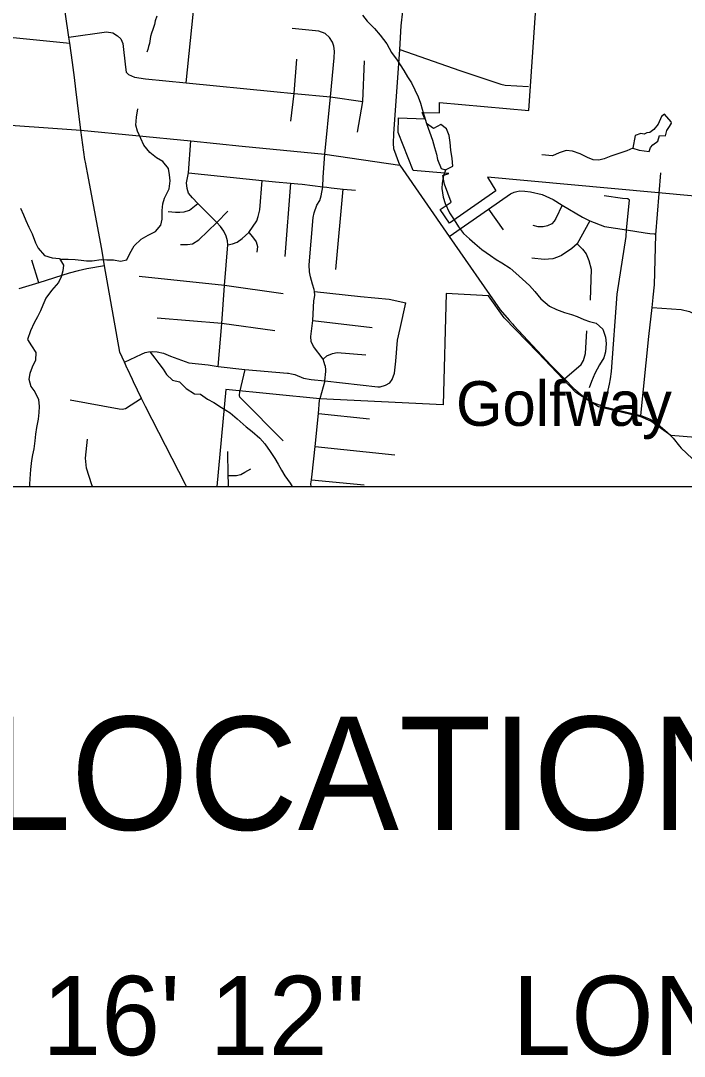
# Model space of a CAD drawing. Extents: x 0 to 34, y 0 to 22.
# Drawn here: x 4.429 to 5.602, y 13.194 to 15.023 of the extents above; entities that cross this region are included whole.
import ezdxf

# ---------------------------------------------------------------- set-up
doc = ezdxf.new("R2010")
doc.units = 0
for name, color, linetype in [('GM_X_City_Street', 7, 'Continuous'), ('GM_X_Corporation', 7, 'Continuous'), ('GM_X_County_Road', 7, 'Continuous'), ('GM_X_Minor_Lake', 7, 'Continuous'), ('GM_X_Minor_River', 7, 'Continuous'), ('GM_X_Township_ROW', 7, 'Continuous'), ('GM_X_Township_Subdivision', 7, 'Continuous'), ('GM_X_Unincorporated_Text', 7, 'Continuous'), ('GM_X_US_Route', 7, 'Continuous'), ('SH_Data', 7, 'Continuous')]:
    doc.layers.add(name, color=color, linetype=linetype)

msp = doc.modelspace()

# ---------------------------------------------------------------- linework, layer by layer
at = {"layer": 'GM_X_City_Street'}
for points in [[(4.8158, 14.3669), (4.8153, 14.3623), (4.8153, 14.3613), (4.8154, 14.3604), (4.8157, 14.3594), (4.816, 14.3588), (4.8185, 14.356), (4.8927, 14.2811)], [(4.9426, 14.2), (4.9417, 14.2051), (4.9428, 14.212), (4.9443, 14.222), (4.9492, 14.2708), (4.9551, 14.3294), (4.9574, 14.353), (4.9577, 14.3554)], [(4.9551, 14.3294), (5.0453, 14.3199)], [(4.9492, 14.2708), (5.0904, 14.2564)], [(5.5934, 14.2713), (5.5961, 14.2678), (5.6155, 14.2498), (5.6358, 14.2115), (5.6405, 14.2)], [(4.7969, 14.2), (4.7964, 14.2007), (4.7962, 14.2064), (4.7959, 14.2197), (4.7949, 14.2619)], [(4.7959, 14.2197), (4.8102, 14.2197), (4.8151, 14.2207), (4.8182, 14.2214), (4.825, 14.2254), (4.8359, 14.2316)], [(4.9428, 14.212), (5.0363, 14.2035)]]:
    msp.add_lwpolyline(points, dxfattribs=at)
at = {"layer": 'GM_X_Corporation'}
msp.add_line((4.7755, 14.2), (7.1307, 14.2), dxfattribs=at)
for points in [[(6.9956, 14.8531), (6.7125, 14.887), (6.701, 14.6468), (6.473, 14.6817), (6.4728, 14.6434), (5.9933, 14.679), (5.254, 14.7467), (5.2688, 14.7224), (5.187, 14.6653), (5.1701, 14.6893), (5.1899, 14.7022), (5.1782, 14.7342), (5.1751, 14.7498), (5.1856, 14.7529), (5.1229, 14.7587), (5.0962, 14.8253), (5.0967, 14.8513), (5.1434, 14.8494), (5.1387, 14.8608), (5.1692, 14.8604), (5.1692, 14.8783), (5.3269, 14.8644), (5.36, 15.3466)], [(6.9956, 14.8531), (6.7125, 14.887), (6.701, 14.6468), (6.473, 14.6817), (6.4728, 14.6434), (5.9933, 14.679), (5.9556, 14.2595), (5.5778, 14.2901), (5.5429, 14.3154), (5.5247, 14.3232), (5.4502, 14.341), (5.4099, 14.3661), (5.3427, 14.4372), (5.2834, 14.4983), (5.256, 14.5372), (5.1809, 14.5414), (5.1758, 14.3448), (4.9577, 14.3554), (4.7915, 14.3718), (4.7755, 14.2)]]:
    msp.add_lwpolyline(points, dxfattribs=at)
at = {"layer": 'GM_X_County_Road'}
for points in [[(5.0993, 14.7678), (5.0886, 14.7969), (5.0877, 14.8064), (5.0885, 14.8231), (5.0988, 14.9724), (5.1017, 15.0142), (5.1101, 15.0924)], [(4.0583, 14.9068), (4.0642, 14.9062), (4.1976, 14.8897), (4.2818, 14.8811), (4.2881, 14.8783), (4.2964, 14.8747), (4.3359, 14.8464), (4.3446, 14.8435), (4.3609, 14.8419), (4.5356, 14.8298)], [(4.5356, 14.8298), (4.7297, 14.8106), (4.8202, 14.8014), (4.9663, 14.7871), (5.0993, 14.7678)], [(5.0993, 14.7678), (5.1865, 14.6418), (5.2762, 14.5124), (5.2922, 14.4942), (5.2988, 14.4868)], [(5.2988, 14.4868), (5.3005, 14.4848), (5.3666, 14.4142), (5.39, 14.3902), (5.4068, 14.3731), (5.4213, 14.3611), (5.4388, 14.3493), (5.4588, 14.3415), (5.4609, 14.341), (5.525, 14.3259), (5.5412, 14.3193), (5.5527, 14.3119), (5.56, 14.306), (5.5714, 14.2962), (5.5823, 14.2858), (5.5934, 14.2713)]]:
    msp.add_lwpolyline(points, dxfattribs=at)
at = {"layer": 'GM_X_Minor_Lake'}
for points in [[(5.5107, 14.7981), (5.5218, 14.7946), (5.5395, 14.7919), (5.542, 14.7991), (5.5463, 14.8035), (5.5551, 14.8102), (5.558, 14.82), (5.5687, 14.8198), (5.5708, 14.8288), (5.5759, 14.8363), (5.579, 14.8419), (5.5783, 14.8442), (5.5668, 14.8581), (5.5614, 14.8537), (5.5554, 14.8402), (5.548, 14.8308), (5.5407, 14.8257), (5.5357, 14.825), (5.5311, 14.8225), (5.5247, 14.8238), (5.5151, 14.8202)], [(5.1462, 14.8416), (5.1569, 14.812), (5.1604, 14.799), (5.1639, 14.7875), (5.1659, 14.778), (5.172, 14.7618), (5.1796, 14.7594)], [(5.1796, 14.7594), (5.1926, 14.7659), (5.1914, 14.7796), (5.1895, 14.7945), (5.1883, 14.8078), (5.1864, 14.8201), (5.1817, 14.832), (5.1716, 14.8394), (5.1585, 14.8325), (5.1462, 14.8416)], [(5.5151, 14.8202), (5.5107, 14.7981)]]:
    msp.add_lwpolyline(points, dxfattribs=at)
at = {"layer": 'GM_X_Minor_River'}
for points in [[(4.6696, 15.0309), (4.6667, 15.0226), (4.6654, 15.0162), (4.6628, 15.0075), (4.6604, 15.0011), (4.6583, 14.995), (4.657, 14.9871), (4.6565, 14.9825), (4.6552, 14.9772), (4.6539, 14.9723), (4.6519, 14.9674)], [(5.0331, 15.0326), (5.0415, 15.0221), (5.0541, 15.0092), (5.0641, 14.9976), (5.0759, 14.9821), (5.0843, 14.967), (5.0946, 14.9535), (5.1063, 14.935), (5.1129, 14.9238), (5.1198, 14.9133), (5.1314, 14.8887), (5.1357, 14.8776), (5.1388, 14.8665), (5.142, 14.855), (5.1462, 14.8416)], [(4.4991, 14.6003), (4.502, 14.6021), (4.513, 14.6018), (4.5255, 14.6011), (4.5358, 14.6001), (4.5456, 14.5991), (4.5551, 14.5989), (4.5715, 14.6015), (4.581, 14.6009), (4.5931, 14.6006), (4.6056, 14.598), (4.6167, 14.6008), (4.6219, 14.6117), (4.6295, 14.6256), (4.6419, 14.6374), (4.6542, 14.644), (4.6673, 14.6505), (4.6767, 14.6617), (4.6789, 14.6723), (4.6792, 14.6879), (4.6803, 14.6993), (4.6832, 14.7098), (4.6916, 14.726), (4.6931, 14.74), (4.6922, 14.7507), (4.6902, 14.7618), (4.6802, 14.7742), (4.6693, 14.7809), (4.657, 14.7903), (4.6467, 14.8031), (4.6413, 14.815), (4.6355, 14.8281), (4.6327, 14.8385), (4.6338, 14.8525), (4.6361, 14.8673)], [(5.5107, 14.7981), (5.5003, 14.793), (5.4846, 14.7881), (5.472, 14.7838), (5.4601, 14.7792), (5.4505, 14.7767), (5.441, 14.777), (5.4305, 14.7814), (5.4178, 14.7878), (5.4042, 14.7927), (5.3928, 14.7937), (5.3806, 14.7895), (5.3687, 14.7844), (5.3501, 14.786)], [(5.1805, 14.7599), (5.1763, 14.7496), (5.1737, 14.7359), (5.1731, 14.7265), (5.1757, 14.7112), (5.1793, 14.7001), (5.1868, 14.6839), (5.1949, 14.6712), (5.2026, 14.6588), (5.2118, 14.6472), (5.2222, 14.6378), (5.2319, 14.6292), (5.2442, 14.6186), (5.2595, 14.608), (5.2696, 14.6013), (5.2793, 14.5953), (5.2939, 14.5859), (5.3043, 14.5772), (5.3159, 14.5663), (5.3285, 14.5554), (5.3377, 14.5445), (5.3485, 14.532), (5.3637, 14.5187), (5.3757, 14.5128), (5.39, 14.5075), (5.4025, 14.5041), (5.4123, 14.5005), (5.4243, 14.4952), (5.4341, 14.4919), (5.4462, 14.4886), (5.4581, 14.478), (5.4623, 14.4639), (5.4636, 14.4528), (5.4625, 14.4384), (5.4595, 14.4274), (5.452, 14.4154), (5.4437, 14.3997), (5.438, 14.3858), (5.4339, 14.3744)], [(4.4285, 14.6917), (4.4343, 14.6801), (4.4383, 14.6702), (4.4437, 14.6582), (4.4495, 14.6463), (4.4555, 14.6306), (4.4599, 14.621), (4.4713, 14.6081), (4.4845, 14.604), (4.4974, 14.6029), (4.5047, 14.591), (4.5034, 14.5811), (4.5008, 14.5705), (4.496, 14.5607), (4.4835, 14.5462), (4.4733, 14.5328), (4.4681, 14.5207), (4.464, 14.5106), (4.4585, 14.5001), (4.4529, 14.4892), (4.4461, 14.4753), (4.4412, 14.4602), (4.4481, 14.4486), (4.4558, 14.437), (4.4551, 14.4237), (4.4495, 14.4113), (4.4454, 14.4), (4.4436, 14.3901), (4.4471, 14.3771), (4.4541, 14.3675), (4.4606, 14.354), (4.4618, 14.3414), (4.4612, 14.3308), (4.4598, 14.3194), (4.4571, 14.3046), (4.4553, 14.2929), (4.4543, 14.2811), (4.452, 14.2667), (4.4499, 14.2561), (4.4481, 14.2463), (4.4462, 14.2304), (4.4451, 14.2137), (4.4448, 14.2042), (4.4449, 14.2)], [(4.658, 14.4378), (4.6661, 14.4269), (4.6731, 14.4173), (4.6808, 14.4076), (4.6867, 14.3979), (4.6974, 14.3878), (4.7095, 14.3852), (4.7214, 14.3731), (4.736, 14.364), (4.7466, 14.3634), (4.7593, 14.3543), (4.7706, 14.3484), (4.784, 14.3397), (4.799, 14.3302), (4.8117, 14.32), (4.8277, 14.3059), (4.8381, 14.2973), (4.8519, 14.2855), (4.8604, 14.2758), (4.8699, 14.2619), (4.878, 14.2499), (4.8838, 14.2395), (4.89, 14.2291), (4.8959, 14.2191), (4.9051, 14.2059), (4.9086, 14.2)]]:
    msp.add_lwpolyline(points, dxfattribs=at)
at = {"layer": 'GM_X_Township_ROW'}
msp.add_lwpolyline([(5.5514, 14.6447), (5.5601, 14.7544)], dxfattribs=at)
at = {"layer": 'GM_X_Township_Subdivision'}
for points in [[(4.7213, 14.9134), (4.7368, 15.0634)], [(4.5144, 14.9937), (4.5806, 15.0034), (4.5916, 15.0014), (4.6001, 14.9964), (4.6058, 14.9909), (4.6098, 14.9829), (4.6143, 14.9412), (4.6153, 14.9319), (4.6193, 14.9277), (4.6303, 14.9232), (4.6496, 14.9204), (4.7213, 14.9134), (4.8763, 14.8977), (4.9125, 14.8942), (4.9763, 14.8887), (5.0335, 14.8802)], [(4.948, 14.5339), (4.9486, 14.5383), (4.948, 14.5448), (4.9477, 14.5482), (4.9445, 14.5578), (4.9411, 14.5708), (4.9394, 14.5792), (4.9386, 14.5918), (4.946, 14.6755), (4.9477, 14.6834), (4.9522, 14.697), (4.9577, 14.7057), (4.9601, 14.7136), (4.9629, 14.7298), (4.9636, 14.7466), (4.9663, 14.7871), (4.9763, 14.8887), (4.9828, 14.9574), (4.9835, 14.9691), (4.9823, 14.9779), (4.9798, 14.9851), (4.9748, 14.9936), (4.9673, 15.0001), (4.9558, 15.0046), (4.909, 15.0094)], [(4.4039, 14.9946), (4.5159, 14.9833)], [(5.0988, 14.9724), (5.2052, 14.9349), (5.2778, 14.9111), (5.285, 14.9094), (5.3266, 14.9065)], [(4.9062, 14.8455), (4.9125, 14.8942), (4.9168, 14.9549)], [(5.0241, 14.8259), (5.0335, 14.8802), (5.0364, 14.952)], [(4.778, 14.4122), (4.7846, 14.4883), (4.7893, 14.5551), (4.7949, 14.6269), (4.7948, 14.6341), (4.792, 14.6426), (4.7882, 14.6512), (4.7823, 14.6597), (4.7757, 14.6663), (4.7423, 14.7), (4.7327, 14.71), (4.7259, 14.7182), (4.7235, 14.7265), (4.722, 14.7368), (4.7257, 14.7543), (4.7297, 14.8106)], [(4.7257, 14.7543), (4.8558, 14.741), (4.8793, 14.7383), (4.9056, 14.7358), (4.919, 14.7346)], [(4.7949, 14.6269), (4.8031, 14.6288), (4.8116, 14.6317), (4.8207, 14.6384), (4.832, 14.649), (4.8462, 14.6696), (4.8487, 14.6772), (4.8517, 14.6892), (4.8558, 14.741)], [(4.9056, 14.7358), (4.8956, 14.6064)], [(4.919, 14.7346), (4.9262, 14.734), (4.9629, 14.7298), (4.9698, 14.729)], [(4.9698, 14.729), (4.978, 14.728), (4.999, 14.7254), (5.0206, 14.7234)], [(4.9862, 14.5837), (4.999, 14.7254)], [(5.1865, 14.6418), (5.2558, 14.6899), (5.2945, 14.7171), (5.3011, 14.7201), (5.3058, 14.7213), (5.3112, 14.7226)], [(5.3112, 14.7226), (5.32, 14.7219), (5.3302, 14.721), (5.3507, 14.7158), (5.37, 14.7072), (5.3858, 14.6971), (5.4218, 14.676), (5.4348, 14.6698), (5.4605, 14.6593), (5.4997, 14.6534), (5.5325, 14.6485), (5.5411, 14.6473), (5.5489, 14.6463), (5.5505, 14.6455), (5.5512, 14.6449), (5.5514, 14.6447)], [(5.4609, 14.341), (5.4694, 14.3808), (5.4714, 14.3907), (5.4731, 14.4032), (5.4832, 14.5398), (5.499, 14.6416), (5.4997, 14.6534), (5.5052, 14.706), (5.5018, 14.7085), (5.4927, 14.7092), (5.4604, 14.7136)], [(4.6894, 14.686), (4.7028, 14.6851), (4.7103, 14.6848), (4.7182, 14.6854), (4.7272, 14.6882), (4.7423, 14.7)], [(5.2558, 14.6899), (5.2816, 14.6534)], [(5.3858, 14.6971), (5.3746, 14.6735), (5.3718, 14.669), (5.3676, 14.6645), (5.36, 14.6608), (5.3524, 14.6588), (5.3434, 14.6592), (5.3348, 14.661)], [(4.7116, 14.6275), (4.7239, 14.628), (4.7326, 14.6291), (4.744, 14.6361), (4.7757, 14.6663), (4.7952, 14.6868)], [(5.4348, 14.6698), (5.4127, 14.6288), (5.4032, 14.6206), (5.3849, 14.6082), (5.378, 14.6052), (5.3697, 14.6025), (5.3541, 14.6013), (5.3326, 14.6035)], [(4.832, 14.649), (4.8388, 14.6411), (4.8454, 14.6326), (4.8478, 14.6244), (4.8465, 14.6139)], [(5.547, 14.5345), (5.5494, 14.5562), (5.5514, 14.6447)], [(5.4127, 14.6288), (5.4218, 14.6196), (5.4282, 14.6111), (5.4331, 14.5995), (5.4372, 14.5843), (5.4352, 14.5291)], [(4.4611, 14.5601), (4.4485, 14.6001)], [(4.5769, 14.5898), (4.5457, 14.5846), (4.5306, 14.5813), (4.5149, 14.5768), (4.4611, 14.5601), (4.426, 14.5494)], [(4.8929, 14.5405), (4.7893, 14.5551), (4.6387, 14.5711)], [(4.948, 14.5448), (5.0294, 14.5356), (5.0801, 14.5313), (5.1095, 14.5245)], [(4.9024, 14.4004), (4.9077, 14.3994), (4.9135, 14.3983), (4.9291, 14.3918), (4.9422, 14.389), (4.9668, 14.3867), (5.0602, 14.3763), (5.0644, 14.3764), (5.074, 14.3794), (5.0815, 14.3832), (5.0858, 14.3891), (5.0899, 14.4005), (5.0923, 14.4215), (5.095, 14.4587), (5.0997, 14.4795), (5.1095, 14.5245)], [(4.9668, 14.3867), (4.9683, 14.4033), (4.9682, 14.4071), (4.9675, 14.4123), (4.9666, 14.4154), (4.9653, 14.4194), (4.9635, 14.4249), (4.9468, 14.4478), (4.9425, 14.4564), (4.9418, 14.4653), (4.9455, 14.4933), (4.9471, 14.5281), (4.948, 14.5339)], [(5.525, 14.3259), (5.5393, 14.4652), (5.545, 14.5162), (5.547, 14.5343), (5.547, 14.5345)], [(5.545, 14.5162), (5.5961, 14.5129), (5.6111, 14.5096), (5.6215, 14.5038), (5.6286, 14.494), (5.6354, 14.4771), (5.6429, 14.4654), (5.6507, 14.4615), (5.6608, 14.4589), (5.6803, 14.4563), (5.7698, 14.4494)], [(4.878, 14.4751), (4.7846, 14.4883), (4.6702, 14.4974)], [(4.9455, 14.4933), (5.05, 14.4811)], [(5.39, 14.3902), (5.4197, 14.416), (5.4234, 14.4231), (5.4269, 14.435), (5.4294, 14.4752)], [(4.6123, 14.4199), (4.6428, 14.4339), (4.6493, 14.4367), (4.6552, 14.4383), (4.6622, 14.4387), (4.6703, 14.4383), (4.6813, 14.4359), (4.6938, 14.4304), (4.7264, 14.4188), (4.7606, 14.4149), (4.778, 14.4122), (4.8252, 14.4072), (4.9008, 14.4007), (4.9024, 14.4004)], [(4.9635, 14.4249), (4.9701, 14.4308), (4.98, 14.4353), (4.9884, 14.437), (5.0392, 14.4331)], [(4.8252, 14.4072), (4.8158, 14.3669)], [(4.9668, 14.3867), (4.9577, 14.3554)], [(4.6428, 14.3557), (4.614, 14.3373), (4.6082, 14.336), (4.603, 14.3367), (4.5162, 14.3529)], [(4.5558, 14.2), (4.5545, 14.2035), (4.5454, 14.2324), (4.5434, 14.2501), (4.5471, 14.2836)]]:
    msp.add_lwpolyline(points, dxfattribs=at)
at = {"layer": 'GM_X_US_Route'}
for points in [[(4.5242, 14.9225), (4.5208, 14.9494), (4.5159, 14.9833), (4.5144, 14.9937), (4.4954, 15.1244), (4.4862, 15.1877), (4.4752, 15.2718), (4.4644, 15.355), (4.4625, 15.3694), (4.4601, 15.3824), (4.4536, 15.436), (4.4509, 15.4477), (4.4494, 15.4539)], [(4.5267, 14.9019), (4.5242, 14.9225)], [(4.5356, 14.8298), (4.5267, 14.9019)], [(4.5435, 14.7729), (4.5425, 14.7781), (4.5356, 14.8298)], [(4.5471, 14.7541), (4.5435, 14.7729)], [(4.7221, 14.2), (4.7203, 14.2037), (4.6497, 14.3417), (4.6428, 14.3557), (4.6284, 14.3852), (4.6266, 14.389), (4.6178, 14.4079), (4.6174, 14.4086), (4.6123, 14.4199), (4.6043, 14.4378), (4.5769, 14.5898), (4.5727, 14.6193), (4.5471, 14.7541)]]:
    msp.add_lwpolyline(points, dxfattribs=at)
at = {"layer": 'SH_Data'}
msp.add_line((2, 14.2), (8.8, 14.2), dxfattribs=at)

# ---------------------------------------------------------------- texts
at = {"layer": 'GM_X_Unincorporated_Text'}
msp.add_text('Golfway', height=0.07898, rotation=0, dxfattribs=at).set_placement((5.1984, 14.3074))
at = {"layer": 'SH_Data'}
for s, height, p in [('LOCATION MAP', 0.2, (4.3691, 13.5938)), ('LATITUDE:  39° 16\' 12"     LONGITUDE:  -84° 34\' 26"', 0.14, (3.071, 13.1959))]:
    msp.add_text(s, height=height, dxfattribs=at).set_placement(p)

doc.saveas('drawing.dxf')
